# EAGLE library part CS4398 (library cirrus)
AUDIO D/A CONVERTOR Stereo 120 dB, 192 kHz, Multi-Bit Audio D/A with Volume Control
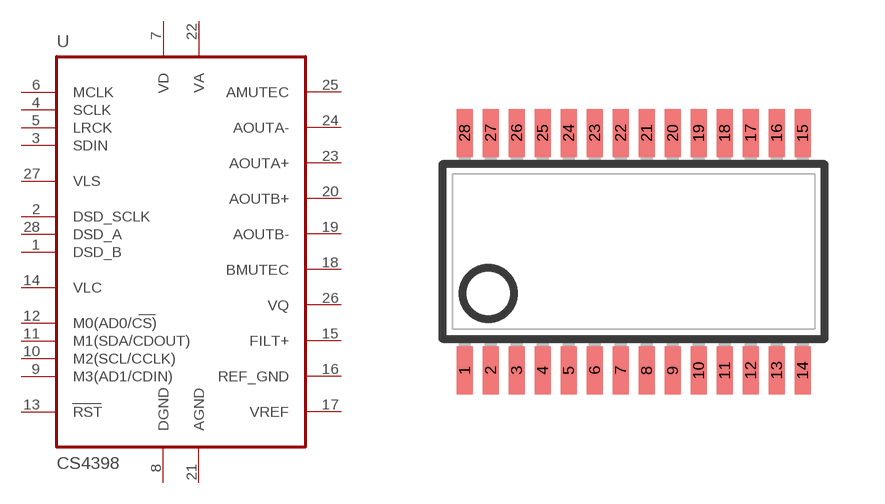
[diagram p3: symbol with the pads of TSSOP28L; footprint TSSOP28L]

Designator prefix U

## CS4398  [TSSOP28L]
1  DSD_B
2  DSD_SCLK
3  SDIN  in
4  SCLK
5  LRCK
6  MCLK  in
7  VD  pwr
8  DGND  pwr
9  M3(AD1/CDIN)  in
10  M2(SCL/CCLK)  in
11  M1(SDA/CDOUT)  in
12  M0(AD0/CS)  in
13  RST  in
14  VLC  pwr
15  FILT+  pas
16  REF_GND  pas
17  VREF  pas
18  BMUTEC  pas
19  AOUTB-  pas
20  AOUTB+  pas
21  AGND  pwr
22  VA  pwr
23  AOUTA+  pas
24  AOUTA-  pas
25  AMUTEC  pas
26  VQ  pas
27  VLS  pwr
28  DSD_A

## Footprint TSSOP28L (pad centres in mm)
Small Shrink Outline Package JEDEC MO-153
smd 0.4 x 1.2: 1 -3.575,-2.97; 2 -2.925,-2.97; 3 -2.275,-2.97; 4 -1.625,-2.97; 5 -0.975,-2.97; 6 -0.325,-2.97; 7 0.325,-2.97; 8 0.975,-2.97; 9 1.625,-2.97; 10 2.275,-2.97; 11 2.925,-2.97; 12 3.575,-2.97; 13 4.225,-2.97; 14 4.875,-2.97; 15 4.875,2.97; 16 4.225,2.97; 17 3.575,2.97; 18 2.925,2.97; 19 2.275,2.97; 20 1.625,2.97; 21 0.975,2.97; 22 0.325,2.97; 23 -0.325,2.97; 24 -0.975,2.97; 25 -1.625,2.97; 26 -2.275,2.97; 27 -2.925,2.97; 28 -3.575,2.97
